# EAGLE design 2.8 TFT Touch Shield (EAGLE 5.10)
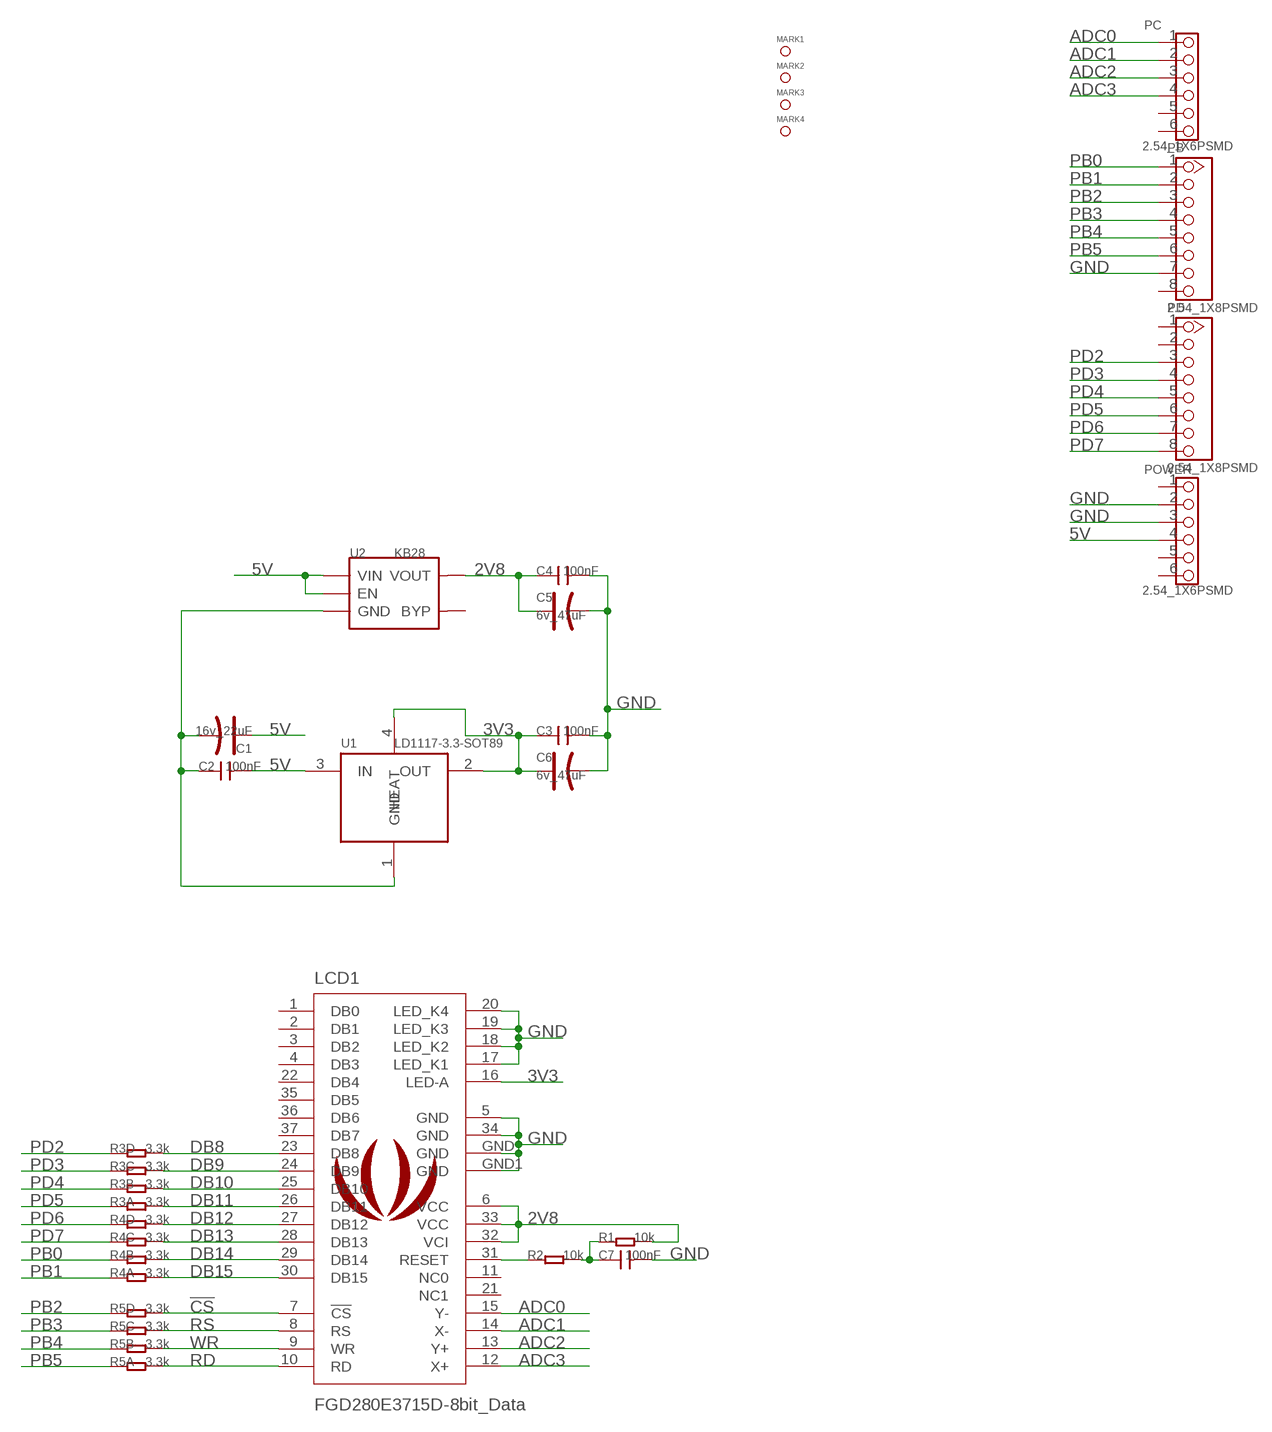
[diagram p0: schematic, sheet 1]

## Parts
C1  16v_22uF  006-CAP_AVX_A  [AVX_A]
C2  100nF  006-C35*40  [0603]
C3  100nF  006-C35*40  [0603]
C4  100nF  006-C35*40  [0603]
C5  6v_47uF  006-CAP_AVX_A  [AVX_A]
C6  6v_47uF  006-CAP_AVX_A  [AVX_A]
C7  100nF  006-C35*40  [0603]
LCD1  FGD280E3715D-8bit_Data  TFT2.8  [TFT2.8]
LOGO1  LOGO_SILK  [LOGO_SILK]
MARK1  MARK  [MARK]
MARK2  MARK  [MARK]
MARK3  MARK  [MARK]
MARK4  MARK  [MARK]
PB  2.54_1X8PSMD  [SMD_8PIN_2.54]
PC  2.54_1X6PSMD  6PSMD  [2.54_6P_SMD]
PD  2.54_1X8PSMD  [SMD_8PIN_2.54]
POWER  2.54_1X6PSMD  6PSMD  [2.54_6P_SMD]
R1  10k  005-R0603  [0603-1]
R2  10k  005-R0603  [0603-1]
R3  3.3k  005-4R_1206  [R1206-8]
R4  3.3k  005-4R_1206  [R1206-8]
R5  3.3k  005-4R_1206  [R1206-8]
U1  LD1117-3.3-SOT89  LD1117SOT89  [SOT89]
U2  KB28  MIC5205  [SOT23-5]

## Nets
2V8: C4.1 C5.+ LCD1.6(VCC) LCD1.32(VCI) LCD1.33(VCC) R1.2 U2.5(VOUT)
3V3: C3.1 C6.+ LCD1.16(LED-A) U1.2(OUT) U1.4(HEAT)
5V: C1.+ C2.2 POWER.4 U1.3(IN) U2.1(VIN) U2.3(EN)
!CS: LCD1.7(!CS) R5.5
ADC0: LCD1.15(Y-) PC.1
ADC1: LCD1.14(X-) PC.2
ADC2: LCD1.13(Y+) PC.3
ADC3: LCD1.12(X+) PC.4
DB8: LCD1.23(DB8) R3.5
DB9: LCD1.24(DB9) R3.6
DB10: LCD1.25(DB10) R3.7
DB11: LCD1.26(DB11) R3.8
DB12: LCD1.27(DB12) R4.5
DB13: LCD1.28(DB13) R4.6
DB14: LCD1.29(DB14) R4.7
DB15: LCD1.30(DB15) R4.8
GND: C1.- C2.1 C3.2 C4.2 C5.- C6.- C7.2 LCD1.5(GND) LCD1.17(LED_K1) LCD1.18(LED_K2) LCD1.19(LED_K3) LCD1.20(LED_K4) LCD1.34(GND) LCD1.GND LCD1.GND1(GND) PB.7 POWER.2 POWER.3 U1.1(GND) U2.2(GND)
N$1: C7.1 R1.1 R2.2
N$2: LCD1.31(RESET) R2.1
PB0: PB.1 R4.2
PB1: PB.2 R4.1
PB2: PB.3 R5.4
PB3: PB.4 R5.3
PB4: PB.5 R5.2
PB5: PB.6 R5.1
PD2: PD.3 R3.4
PD3: PD.4 R3.3
PD4: PD.5 R3.2
PD5: PD.6 R3.1
PD6: PD.7 R4.4
PD7: PD.8 R4.3
RD: LCD1.10(RD) R5.8
RS: LCD1.8(RS) R5.6
WR: LCD1.9(WR) R5.7
Unconnected: LCD1.1(DB0) LCD1.2(DB1) LCD1.3(DB2) LCD1.4(DB3) LCD1.11(NC0) LCD1.21(NC1) LCD1.22(DB4) LCD1.35(DB5) LCD1.36(DB6) LCD1.37(DB7) PB.8 PC.5 PC.6 PD.1 PD.2 POWER.1 POWER.5 POWER.6 U2.4(BYP)

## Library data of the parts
C1 C5 C6 = Discrete:006-CAP*: Electrolytic Capacitors,Tantalum Capacitors and Super Capacitors
C2-C4 C7 = Discrete:006-C*: Ceramic Capacitors
LCD1 = EXT_moudle:TFT2.8
LOGO1 = logo:LOGO_SILK
MARK1-MARK4 = Discrete:MARK
PB PD = Connector:2.54_1X8P
PC POWER = Connector:6P
R1 R2 = Discrete:005-R*
R3-R5 = Discrete:005-4R*: Resistor Array
U1 = ICs_v54:LD1117
U2 = IC:MIC5205: The MIC5205 is an efficient linear voltage regulator with ultra-low-noise output, very low dropout voltage (typically 17mV at light loads and 165mV at 150mA), and very low ground current (600µA at 100mA output). The MIC5205 offers better than 1% initial accuracy. datasheet here: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

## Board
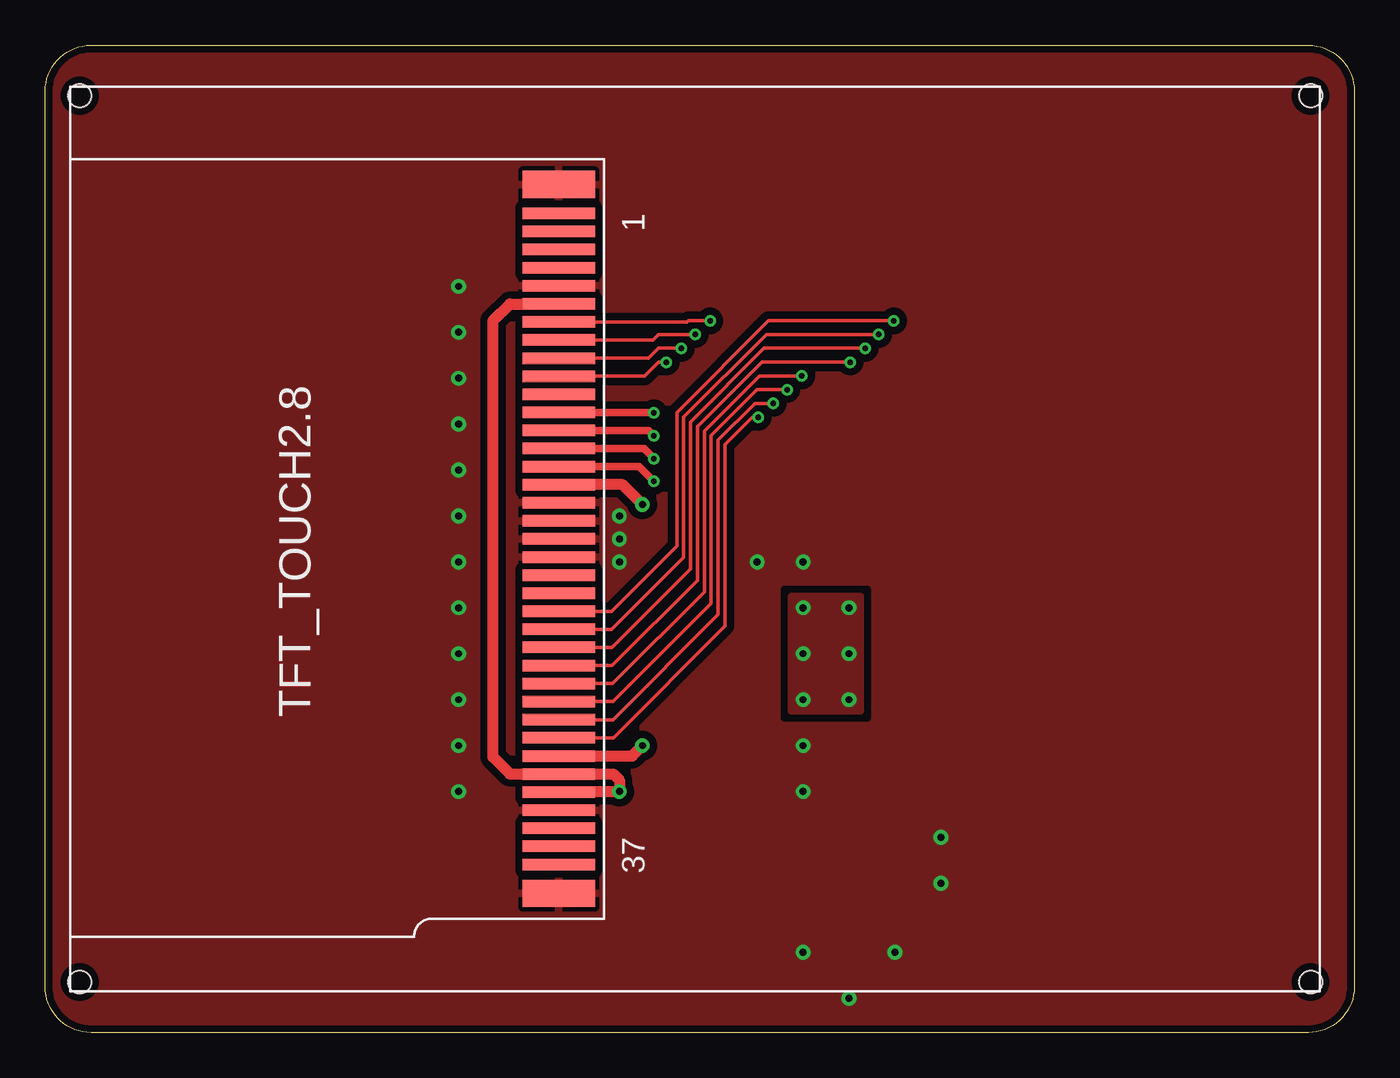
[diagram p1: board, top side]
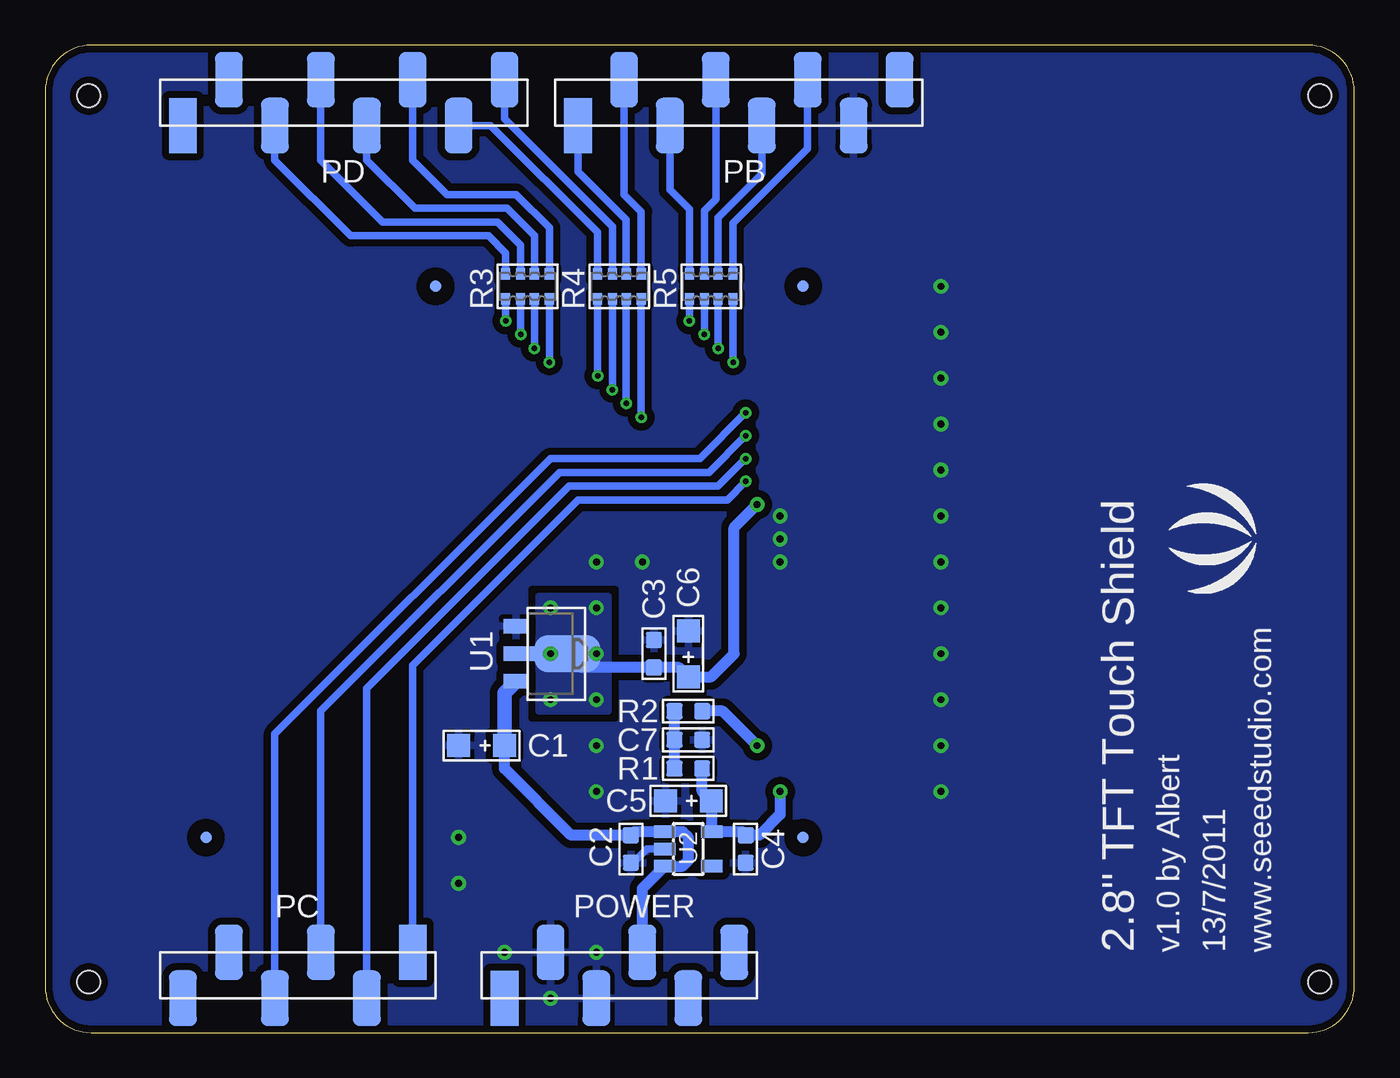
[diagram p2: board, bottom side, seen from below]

Size 72.39 x 54.61 mm. Coordinates in mm from the lower left corner, seen from the top.
Outline: 0,52.07 arc-90 2.54,54.61 69.85,54.61 arc-90 72.39,52.07 72.39,2.54 arc-90 69.85,0 2.54,0 arc-90 0,2.54 0,52.07
Copper layers (1*16): Top 0.035mm / dielectric 1.5mm / Bottom 0.035mm
Design rules "rule_manufacture *": minimum track width 8mil, minimum drill 12mil, track to track 6mil, track to pad 6mil, pad to pad 6mil, via to via 8mil, smd to smd 0mil, copper to edge 10mil, drill to drill 10mil, minimum pad ring 10mil, minimum via ring 6mil, stop-mask expansion 2mil, vias tented up to drill 25mil, thermal gap 10mil
tRestrict: area 27.4,26.2 to 29.3,29.3

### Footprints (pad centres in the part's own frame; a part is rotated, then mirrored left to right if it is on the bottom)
AVX_A = smd 1.27 x 1.27: + -1.27,0; - 1.27,0
0603 = smd 0.889 x 0.889: 1 -0.762,0; 2 0.762,0
TFT2.8 = smd 4 x 0.635: 1 27,43.019; 2 27,42.019; 3 27,41.019; 4 27,40.019; 5 27,39.019; 6 27,38.019; 7 27,37.019; 8 27,36.019; 9 27,35.019; 10 27,34.019; 11 27,33.019; 12 27,32.019; 13 27,31.019; 14 27,30.019; 15 27,29.019; 16 27,28.019; 17 27,27.019; 18 27,26.019; 19 27,25.019; 20 27,24.019; 21 27,23.019; 22 27,22.019; 23 27,21.019; 24 27,20.019; 25 27,19.019; 26 27,18.019; 27 27,17.019; 28 27,16.019; 29 27,15.019; 30 27,14.019; 31 27,13.019; 32 27,12.019; 33 27,11.019; 34 27,10.019; 35 27,9.019; 36 27,8.019; 37 27,7.019 | smd 4 x 1.516: GND 27,5.419; GND1 27,44.619 | hole 1.27: 0.508,49.53; 68.58,49.53; 68.58,0.508; 0.508,0.508
MARK = smd 0.635 x 0.635: P$1 0,0
SMD_8PIN_2.54 = smd 3.048 x 1.524: 1 -1.27,8.89; 2 1.27,6.35; 3 -1.27,3.81; 4 1.27,1.27; 5 -1.27,-1.27; 6 1.27,-3.81; 7 -1.27,-6.35; 8 1.27,-8.89
2.54_6P_SMD = smd 3.048 x 1.524: 1 -1.27,6.35; 2 1.27,3.81; 3 -1.27,1.27; 4 1.27,-1.27; 5 -1.27,-3.81; 6 1.27,-6.35
0603-1 = smd 0.889 x 0.889: 1 -0.762,0; 2 0.762,0
R1206-8 = smd 0.508 x 0.635: 1 -1.206,-0.699; 2 -0.381,-0.699; 3 0.381,-0.699; 4 1.206,-0.699; 5 1.206,0.699; 6 0.381,0.699; 7 -0.381,0.699; 8 -1.206,0.699
SOT89 = smd 0.8 x 1.4: 1 -1.524,-1.905; 3 1.524,-1.905 | smd 0.8 x 1.9: 2 0,-1.651 | smd 2.032 x 3.65: 4 0,0.94
SOT23-5 = smd 0.69 x 1.2: 1 -0.95,-1.3; 2 0,-1.3; 3 0.95,-1.3; 4 0.95,1.3; 5 -0.95,1.3

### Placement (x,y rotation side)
C1  48.26,15.88 180 bottom
C2  40.01,10.16 90 bottom
C3  38.73,20.96 90 bottom
C4  33.66,10.16 270 bottom
C5  36.83,12.83 180 bottom
C6  36.83,20.96 90 bottom
C7  36.83,16.19 0 bottom
LCD1  1.4,2.29 0 top
LOGO1  7.11,27.31 90 bottom
MARK1  50.8,41.27 0 bottom
MARK2  30.48,41.27 0 bottom
MARK3  30.48,10.79 0 bottom
MARK4  63.5,10.79 0 bottom
PB  34.04,51.43 90 bottom
PC  58.42,3.17 270 bottom
PD  55.88,51.43 90 bottom
POWER  40.64,3.17 90 bottom
R1  36.83,14.61 0 bottom
R2  36.83,17.78 180 bottom
R3  45.72,41.27 180 bottom
R4  40.64,41.27 180 bottom
R5  35.56,41.27 180 bottom
U1  44.45,20.96 270 bottom
U2  36.83,10.16 270 bottom

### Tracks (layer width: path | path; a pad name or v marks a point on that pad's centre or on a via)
2V8  (via drill 0.38 pad 0.81)
  Top 0.61: LCD1.33 31.72,13.3 v31.75,13.33 31.75,13.97 31.41,14.3 LCD1.32 25.7,14.3 24.77,15.24 24.77,39.37 25.7,40.3 LCD1.6
  Bottom 0.61: v31.75,13.33 31.75,12.06 32.89,10.92 C4.1 33.84,11.11 U2.5 35.53,12.8 C5.+ 36.07,13.33 R1.2
3V3  (via drill 0.38 pad 0.81)
  Top 0.61: LCD1.16 31.93,30.31 v33.02,29.21
  Bottom 0.61: U1.2 v44.45,20.96 U1.4 42.75,20.19 C3.1 37.34,20.19 C6.+ 35.56,19.69 34.29,20.96 34.29,27.94 v33.02,29.21
  other vias: 44.45,23.5 41.91,23.5 41.91,20.96 41.91,18.42 44.45,18.42
  pour Bottom (isolate 0.406, no thermals): 41.27,17.78 41.27,24.13 45.09,24.13 45.09,17.78
  pour Top (isolate 0.406): 41.27,17.78 41.27,24.13 45.09,24.13 45.09,17.78
5V
  Bottom 0.61: POWER.4 39.37,7.97 U2.3 37.15,9.21 36.83,9.53 36.83,10.79 37.15,11.11 U2.1 39.82,11.11 C2.2 43.31,10.92 46.99,14.61 C1.+
  Bottom 0.813: C1.+ 46.99,18.8 U1.3
!CS  (via drill 0.3 pad 0.64)
  Top 0.203: LCD1.7 35.49,39.3 35.56,39.37 v36.77,39.37
  Bottom 0.406: v36.77,39.37 R5.5
ADC0  (via drill 0.3 pad 0.64)
  Top 0.406: LCD1.15 32.83,31.31 v33.66,30.48
  Bottom 0.406: PC.1 52.07,20.32 42.93,29.46 34.67,29.46 v33.66,30.48
ADC1  (via drill 0.3 pad 0.64)
  Top 0.406: LCD1.14 33.1,32.3 v33.66,31.75
  Bottom 0.406: PC.2 54.61,19.05 43.43,30.23 35.18,30.23 v33.66,31.75
ADC2  (via drill 0.3 pad 0.64)
  Top 0.406: LCD1.13 33.37,33.3 v33.66,33.02
  Bottom 0.406: PC.3 57.15,17.78 43.94,30.99 35.69,30.99 v33.66,33.02
ADC3  (via drill 0.3 pad 0.64)
  Top 0.406: LCD1.12 33.64,34.3 v33.66,34.29
  Bottom 0.406: PC.4 59.69,16.51 44.45,31.75 36.2,31.75 v33.66,34.29
DB8  (via drill 0.3 pad 0.64)
  Top 0.203: v46.93,39.37 40.01,39.37 34.92,34.29 34.92,26.92 31.31,23.31 LCD1.23
  Bottom 0.406: v46.93,39.37 R3.5
DB9  (via drill 0.3 pad 0.64)
  Top 0.203: v46.1,38.61 39.88,38.61 35.31,34.04 35.31,26.29 31.32,22.31 LCD1.24
  Bottom 0.406: v46.1,38.61 R3.6
DB10  (via drill 0.3 pad 0.64)
  Top 0.203: v45.34,37.85 39.75,37.85 35.69,33.78 35.69,25.65 31.34,21.31 LCD1.25
  Bottom 0.406: v45.34,37.85 R3.7
DB11  (via drill 0.3 pad 0.64)
  Top 0.203: v44.51,37.08 39.62,37.08 36.07,33.53 36.07,25.02 31.35,20.31 LCD1.26
  Bottom 0.406: v44.51,37.08 R3.8
DB12  (via drill 0.3 pad 0.64)
  Top 0.203: v41.85,36.32 39.5,36.32 36.45,33.27 36.45,24.38 31.37,19.31 LCD1.27
  Bottom 0.406: v41.85,36.32 R4.5
DB13  (via drill 0.3 pad 0.64)
  Top 0.203: v41.02,35.56 39.37,35.56 36.83,33.02 36.83,23.75 31.39,18.31 LCD1.28
  Bottom 0.406: v41.02,35.56 R4.6
DB14  (via drill 0.3 pad 0.64)
  Top 0.203: v40.26,34.8 39.24,34.8 37.21,32.77 37.21,23.11 31.4,17.31 LCD1.29
  Bottom 0.406: v40.26,34.8 R4.7
DB15  (via drill 0.3 pad 0.64)
  Top 0.203: v39.43,34.04 39.12,34.04 37.59,32.51 37.59,22.48 31.42,16.3 LCD1.30
  Bottom 0.406: v39.43,34.04 R4.8
GND  (via drill 0.38 pad 0.81)
  Bottom 0.406: U2.2 39.12,10.16 39.88,9.4 C2.1
  other vias: 39.37,26.04 41.91,26.04 31.75,26.04 31.75,28.58 31.75,27.31 41.91,15.88 49.53,8.26 49.53,10.79 44.45,1.91 41.91,4.45 46.99,4.45 41.91,13.33 22.86,15.88 22.86,18.42 22.86,20.96 22.86,23.5 22.86,26.04 22.86,28.58 22.86,31.12 22.86,33.66 22.86,36.2 22.86,38.73 22.86,41.27 22.86,13.33
  pour Top: -6.35,53.98 -5.08,53.98 -5.08,52.7 -6.35,52.7
  pour Bottom (isolate 0.406, rank 6): 0,54.61 72.39,54.61 72.39,0 0,0
  pour Top (isolate 0.406, rank 6): 0,54.61 72.39,54.61 72.39,0 0,0
N$1
  Bottom 0.61: R1.1 C7.1 R2.2
N$2  (via drill 0.38 pad 0.81)
  Top 0.61: LCD1.31 32.45,15.3 v33.02,15.88
  Bottom 0.61: R2.1 34.92,17.78 v33.02,15.88
PB0
  Bottom 0.406: R4.2 40.26,44.96 42.93,47.62 PB.1
PB1
  Bottom 0.406: R4.1 39.43,45.4 40.39,46.35 PB.2
PB2
  Bottom 0.406: R5.4 36.77,45.53 37.85,46.61 PB.3
PB3
  Bottom 0.406: R5.3 35.94,45.47 35.31,46.1 PB.4
PB4
  Bottom 0.406: R5.2 35.18,45.09 32.77,47.5 PB.5
PB5
  Bottom 0.406: R5.1 34.35,44.77 30.23,48.89 PB.6
PD2
  Bottom 0.406: R3.4 46.93,43.12 47.88,44.07 55.5,44.07 59.69,48.26 PD.3
PD3
  Bottom 0.406: R3.3 46.1,43.56 47.37,44.83 53.72,44.83 57.15,48.26 PD.4
PD4
  Bottom 0.406: R3.2 45.34,44.07 46.86,45.59 51.94,45.59 54.61,48.26 PD.5
PD5
  Bottom 0.406: R3.1 44.51,44.51 46.35,46.35 50.16,46.35 52.07,48.26 PD.6
PD6
  Bottom 0.406: R4.4 41.85,44.26 47.75,50.16 PD.7
PD7
  Bottom 0.406: R4.3 41.02,44.58 46.99,50.55 PD.8
RD  (via drill 0.3 pad 0.64)
  Top 0.203: LCD1.10 33.13,36.3 33.91,37.08 v34.35,37.08
  Bottom 0.406: v34.35,37.08 R5.8
RS  (via drill 0.3 pad 0.64)
  Top 0.203: LCD1.8 33.61,38.3 33.91,38.61 v35.94,38.61
  Bottom 0.406: v35.94,38.61 R5.6
WR  (via drill 0.3 pad 0.64)
  Top 0.203: LCD1.9 33.37,37.3 33.91,37.85 v35.18,37.85
  Bottom 0.406: v35.18,37.85 R5.7

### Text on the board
bPlace: www.seeedstudio.com | 13/7/2011 | v1.0 by Albert | 2.8" TFT Touch Shield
